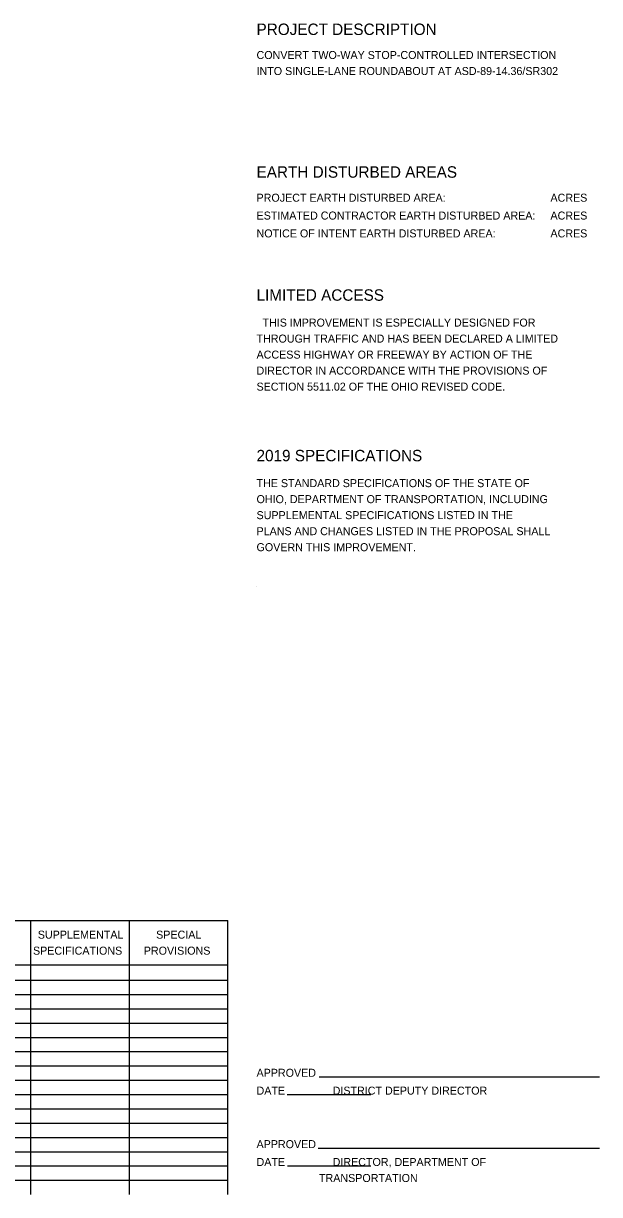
# Model space of a CAD drawing. Extents: x 0 to 72, y -85 to 22.
# Drawn here: x 61.62 to 71.7, y -12.31 to 8.17 of the extents above; entities that cross this region are included whole.
import ezdxf

# ---------------------------------------------------------------- set-up
doc = ezdxf.new("R2010")
doc.units = 0
doc.layers.add('GM_X_Township', color=7, linetype='Continuous')

msp = doc.modelspace()

# ---------------------------------------------------------------- linework, layer by layer
at = {"layer": 'GM_X_Township'}
for p, q in [((65.696, -1.668), (65.696, -1.668)), ((51.746, -7.517), (65.196, -7.517)), ((61.746, -12.309), (61.746, -7.517)), ((63.471, -12.309), (63.471, -7.517)), ((65.196, -12.309), (65.196, -7.517)), ((51.746, -8.288), (65.196, -8.288)), ((51.746, -8.559), (65.196, -8.559)), ((51.746, -8.809), (65.196, -8.809)), ((51.746, -9.059), (65.196, -9.059)), ((51.746, -9.309), (65.196, -9.309)), ((51.746, -9.559), (65.196, -9.559)), ((51.746, -9.809), (65.196, -9.809)), ((51.746, -10.059), (65.196, -10.059)), ((51.746, -10.309), (65.196, -10.309)), ((66.791, -10.249), (71.696, -10.249)), ((51.746, -10.559), (65.196, -10.559)), ((66.229, -10.561), (67.697, -10.561)), ((51.746, -10.809), (65.196, -10.809)), ((51.746, -11.059), (65.196, -11.059)), ((51.746, -11.309), (65.196, -11.309)), ((51.746, -11.559), (65.196, -11.559)), ((66.776, -11.497), (71.696, -11.497)), ((51.746, -11.809), (65.196, -11.809)), ((66.238, -11.809), (67.697, -11.809)), ((51.746, -12.059), (65.196, -12.059))]:
    msp.add_line(p, q, dxfattribs=at)

# ---------------------------------------------------------------- texts
for s, height, p in [('PROJECT DESCRIPTION', 0.2, (65.696, 7.972)), ('CONVERT TWO-WAY STOP-CONTROLLED INTERSECTION', 0.14, (65.696, 7.552)), ('INTO SINGLE-LANE ROUNDABOUT AT ASD-89-14.36/SR302', 0.14, (65.696, 7.272)), ('EARTH DISTURBED AREAS', 0.2, (65.696, 5.476)), ('PROJECT EARTH DISTURBED AREA:', 0.14, (65.696, 5.056)), ('     ACRES', 0.14, (70.577, 5.056)), ('ESTIMATED CONTRACTOR EARTH DISTURBED AREA:', 0.14, (65.696, 4.744)), ('     ACRES', 0.14, (70.577, 4.744)), ('NOTICE OF INTENT EARTH DISTURBED AREA:', 0.14, (65.696, 4.432)), ('     ACRES', 0.14, (70.577, 4.432)), ('LIMITED ACCESS', 0.2, (65.696, 3.324)), ('  THIS IMPROVEMENT IS ESPECIALLY DESIGNED FOR', 0.14, (65.696, 2.872)), ('THROUGH TRAFFIC AND HAS BEEN DECLARED A LIMITED', 0.14, (65.696, 2.592)), ('ACCESS HIGHWAY OR FREEWAY BY ACTION OF THE', 0.14, (65.696, 2.312)), ('DIRECTOR IN ACCORDANCE WITH THE PROVISIONS OF', 0.14, (65.696, 2.032)), ('SECTION 5511.02 OF THE OHIO REVISED CODE.', 0.14, (65.696, 1.752)), ('2019 SPECIFICATIONS', 0.2, (65.696, 0.516)), ('THE STANDARD SPECIFICATIONS OF THE STATE OF', 0.14, (65.696, 0.064)), ('OHIO, DEPARTMENT OF TRANSPORTATION, INCLUDING', 0.14, (65.696, -0.216)), ('SUPPLEMENTAL SPECIFICATIONS LISTED IN THE', 0.14, (65.696, -0.496)), ('PLANS AND CHANGES LISTED IN THE PROPOSAL SHALL', 0.14, (65.696, -0.776)), ('GOVERN THIS IMPROVEMENT.', 0.14, (65.696, -1.056)), ('SUPPLEMENTAL', 0.14, (61.87, -7.833)), ('SPECIAL', 0.14, (63.94, -7.833)), ('SPECIFICATIONS', 0.14, (61.786, -8.113)), ('PROVISIONS', 0.14, (63.724, -8.113)), ('APPROVED', 0.14, (65.696, -10.249)), ('DATE                DISTRICT DEPUTY DIRECTOR', 0.14, (65.696, -10.561)), ('APPROVED', 0.14, (65.696, -11.497)), ('DATE                DIRECTOR, DEPARTMENT OF', 0.14, (65.696, -11.809)), ('                     TRANSPORTATION', 0.14, (65.696, -12.089))]:
    msp.add_text(s, height=height, dxfattribs=at).set_placement(p)

doc.saveas('drawing.dxf')
